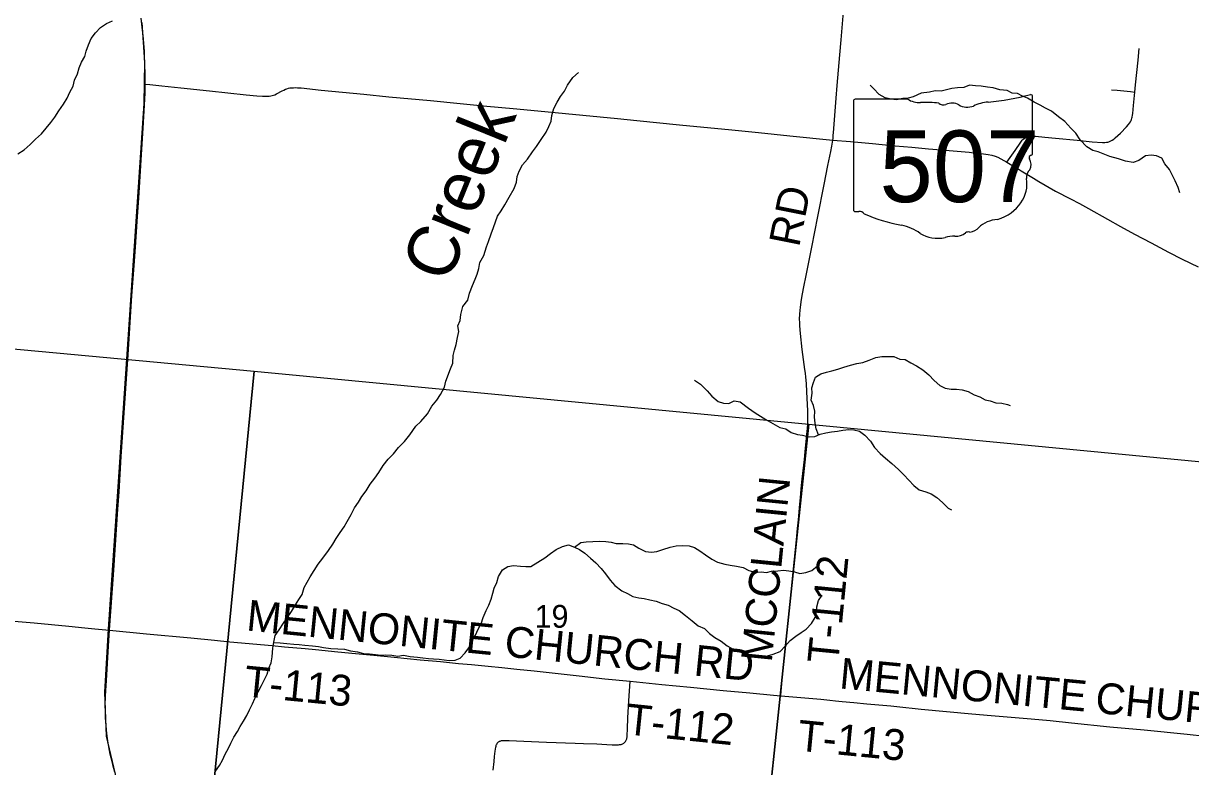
# Model space of a CAD drawing. Extents: x 0 to 1101, y 0 to 440.
# Drawn here: x 840.814 to 842.962, y 375.148 to 376.517 of the extents above; entities that cross this region are included whole.
import ezdxf

# ---------------------------------------------------------------- set-up
doc = ezdxf.new("R2010")
doc.units = 0
for name, color, linetype in [('GM_X_County_Road', 7, 'Continuous'), ('GM_X_Minor_River', 7, 'Continuous'), ('GM_X_Minor_River_Text', 7, 'Continuous'), ('GM_X_Rail_Line', 7, 'Continuous'), ('GM_X_Section', 7, 'Continuous'), ('GM_X_Section_Text', 7, 'Continuous'), ('GM_X_State_Location', 7, 'Continuous'), ('GM_X_State_Route', 7, 'Continuous'), ('GM_X_State_Shield', 7, 'Continuous'), ('GM_X_Township_Road', 7, 'Continuous'), ('GM_X_Township_Road_Text', 7, 'Continuous'), ('GM_X_US_Route', 7, 'Continuous')]:
    doc.layers.add(name, color=color, linetype=linetype)

msp = doc.modelspace()

# ---------------------------------------------------------------- linework, layer by layer
at = {"layer": 'GM_X_County_Road'}
msp.add_lwpolyline([(840.7823, 375.4177), (840.8341, 375.4129), (840.8655, 375.4099), (840.8973, 375.4069), (840.927, 375.4041), (840.9455, 375.4024), (840.9726, 375.3998)], dxfattribs=at)
at = {"layer": 'GM_X_Minor_River'}
for points in [[(840.8037, 376.2766), (840.8153, 376.2835), (840.8262, 376.2938), (840.836, 376.3034), (840.8473, 376.3134), (840.8556, 376.3238), (840.8642, 376.3338), (840.8721, 376.3439), (840.8793, 376.3558), (840.888, 376.3678), (840.8943, 376.3786), (840.8996, 376.3899), (840.9056, 376.4011), (840.9078, 376.4121), (840.9135, 376.4234), (840.9169, 376.4347), (840.9209, 376.4449), (840.9273, 376.4553), (840.9295, 376.4655), (840.9336, 376.4768), (840.9385, 376.4885), (840.9464, 376.4989), (840.9558, 376.5089), (840.9671, 376.5166), (840.9778, 376.5212)], [(841.6998, 376.1828), (841.7075, 376.1965), (841.7172, 376.2128), (841.7215, 376.2242), (841.7227, 376.2348), (841.7262, 376.2447), (841.7324, 376.2561), (841.7412, 376.2667), (841.7509, 376.28), (841.7582, 376.2898), (841.7667, 376.3027), (841.7756, 376.3163), (841.7806, 376.3266), (841.7849, 376.3368), (841.7865, 376.3467), (841.79, 376.3597), (841.7959, 376.3714), (841.802, 376.382), (841.8097, 376.3919), (841.8152, 376.4029), (841.8252, 376.4169), (841.8356, 376.426)], [(842.9415, 376.2046), (842.9386, 376.2145), (842.9334, 376.2268), (842.9277, 376.2379), (842.9225, 376.2478), (842.9142, 376.2578), (842.9086, 376.2682), (842.8987, 376.2728), (842.8892, 376.2737), (842.8786, 376.2726), (842.8663, 376.2644), (842.8556, 376.2603), (842.8415, 376.2631), (842.8286, 376.267), (842.8127, 376.2713), (842.8009, 376.2764), (842.7914, 376.2799), (842.7819, 376.2823), (842.7706, 376.2893), (842.7585, 376.3019), (842.7502, 376.3142), (842.7412, 376.3238), (842.7303, 376.3358), (842.7182, 376.3446), (842.7053, 376.3547), (842.6947, 376.3605), (842.6845, 376.3663), (842.6738, 376.3713), (842.6617, 376.3787), (842.6522, 376.3826), (842.6428, 376.3873), (842.6333, 376.3881), (842.6238, 376.3928), (842.6108, 376.3944), (842.5983, 376.398), (842.588, 376.3992), (842.5763, 376.4008), (842.566, 376.4013), (842.555, 376.4029), (842.5443, 376.3988), (842.5324, 376.3982), (842.5222, 376.3968), (842.5126, 376.3942), (842.5027, 376.392), (842.4917, 376.3925), (842.481, 376.3899), (842.4661, 376.3881), (842.4512, 376.3814), (842.4417, 376.3788), (842.4318, 376.3785), (842.4207, 376.376), (842.4104, 376.3768), (842.3998, 376.3792), (842.3888, 376.3858), (842.3782, 376.3969), (842.3718, 376.4031)], [(841.1677, 375.1402), (841.1747, 375.1508), (841.1801, 375.1606), (841.1852, 375.1712), (841.1913, 375.1822), (841.1956, 375.1917), (841.2014, 375.2027), (841.208, 375.213), (841.2126, 375.2225), (841.2188, 375.2319), (841.225, 375.2429), (841.2297, 375.2532), (841.2355, 375.2638), (841.2401, 375.2737), (841.246, 375.2862), (841.2521, 375.2976), (841.2568, 375.3078), (841.2626, 375.3188), (841.2658, 375.3295), (841.27, 375.3397), (841.272, 375.3507), (841.2729, 375.3667), (841.2749, 375.3778), (841.277, 375.39), (841.2843, 375.4002), (841.2924, 375.4123), (841.2993, 375.4225), (841.3074, 375.4343), (841.3148, 375.446), (841.3209, 375.4559), (841.3267, 375.4654), (841.3307, 375.4783), (841.3361, 375.4881), (841.3419, 375.4976), (841.3492, 375.5097), (841.3562, 375.5211), (841.3647, 375.5325), (841.3751, 375.5461), (841.3832, 375.5578), (841.3897, 375.5685), (841.3971, 375.5795), (841.404, 375.5901), (841.4098, 375.5999), (841.4171, 375.6128), (841.4233, 375.625), (841.4303, 375.6352), (841.4365, 375.6454), (841.4446, 375.656), (841.4519, 375.6685), (841.4604, 375.6795), (841.4681, 375.6901), (841.4762, 375.7026), (841.4851, 375.7147), (841.4947, 375.7242), (841.5039, 375.7359), (841.515, 375.7472), (841.5251, 375.7594), (841.5359, 375.7749), (841.5454, 375.7836), (841.5578, 375.7979), (841.5655, 375.812), (841.5747, 375.8233), (841.5817, 375.8336), (841.5887, 375.8472), (841.5914, 375.8582), (841.6, 375.8807), (841.6043, 375.8913), (841.6048, 375.905), (841.6072, 375.9149), (841.6103, 375.9255), (841.6127, 375.9385), (841.6151, 375.9491), (841.6136, 375.9598), (841.6175, 375.9697), (841.6188, 375.9807), (841.6227, 375.9952), (841.632, 376.0073), (841.6347, 376.0199), (841.6406, 376.0343), (841.6449, 376.0457), (841.6491, 376.0552), (841.6519, 376.0655), (841.6539, 376.0765), (841.6609, 376.0894), (841.666, 376.1054), (841.6695, 376.1152), (841.6745, 376.1293), (841.6792, 376.1407), (841.6827, 376.1513), (841.6866, 376.1616), (841.6932, 376.1714), (841.6998, 376.1828)], [(842.277, 375.7592), (842.2729, 375.7704), (842.2707, 375.7807), (842.2697, 375.7918), (842.2702, 375.8028), (842.268, 375.8131), (842.2635, 375.8231), (842.2655, 375.8356), (842.2648, 375.8456), (842.2676, 375.8558), (842.2711, 375.8653), (842.2814, 375.8717), (842.2914, 375.8747), (842.3013, 375.8769), (842.3123, 375.8798), (842.3238, 375.8835), (842.336, 375.8872), (842.3475, 375.8905), (842.3585, 375.8924), (842.3704, 375.8968), (842.3822, 375.9017), (842.3937, 375.9031), (842.4047, 375.9034), (842.4157, 375.9033), (842.4264, 375.8986), (842.4366, 375.8977), (842.4465, 375.8919), (842.4575, 375.8865), (842.4688, 375.8791), (842.4798, 375.8699), (842.49, 375.8595), (842.5002, 375.8503), (842.51, 375.8448), (842.5207, 375.8432), (842.5309, 375.8435), (842.5412, 375.8423), (842.5522, 375.8387), (842.5632, 375.8329), (842.5735, 375.8294), (842.5833, 375.8236), (842.5928, 375.8216), (842.6034, 375.8181), (842.6145, 375.8172), (842.6244, 375.8148), (842.6297, 375.8129)], [(842.0487, 375.8597), (842.0597, 375.8524), (842.0721, 375.8405), (842.0808, 375.8305), (842.0925, 375.8208), (842.102, 375.8177), (842.1119, 375.8168), (842.1215, 375.8217), (842.1329, 375.8197), (842.1484, 375.8081), (842.1601, 375.7996), (842.1798, 375.7872), (842.1927, 375.7803), (842.2056, 375.7725), (842.2166, 375.7701), (842.2264, 375.7636), (842.2382, 375.7596), (842.2477, 375.7588), (842.2598, 375.7553), (842.2701, 375.7563), (842.2801, 375.7604), (842.2904, 375.763), (842.3007, 375.7648), (842.3117, 375.7658), (842.3216, 375.7676), (842.3327, 375.7691), (842.3422, 375.7686), (842.3521, 375.7662), (842.3623, 375.7585), (842.3725, 375.7477), (842.38, 375.7359), (842.3902, 375.7251), (842.4, 375.7162), (842.4117, 375.7066), (842.4238, 375.6954), (842.434, 375.6858), (842.4434, 375.6758), (842.4521, 375.6658), (842.4623, 375.6581), (842.4741, 375.6546), (842.4839, 375.6507), (842.4945, 375.6441), (842.5051, 375.6348), (842.5153, 375.6245), (842.5217, 375.621)], [(841.2748, 375.3768), (841.2863, 375.3761), (841.2985, 375.3753), (841.3118, 375.374), (841.3214, 375.3732), (841.332, 375.3719), (841.3457, 375.371), (841.3567, 375.3694), (841.3662, 375.3678), (841.3799, 375.3661), (841.3925, 375.3656), (841.4047, 375.3644), (841.4161, 375.3616), (841.429, 375.36), (841.4396, 375.3568), (841.4507, 375.3563), (841.4621, 375.3547), (841.4716, 375.3539), (841.4811, 375.3541), (841.4921, 375.3537), (841.5028, 375.352), (841.5135, 375.3535), (841.5256, 375.3515), (841.5393, 375.3498), (841.5488, 375.349), (841.5591, 375.3477), (841.5686, 375.3469), (841.5789, 375.346), (841.5971, 375.3439), (841.6082, 375.3446), (841.6177, 375.3479), (841.627, 375.3581), (841.6354, 375.3699), (841.6393, 375.3794), (841.6459, 375.3904), (841.6509, 375.4018), (841.656, 375.4112), (841.6599, 375.423), (841.6657, 375.4359), (841.6704, 375.4454), (841.6747, 375.4568), (841.6778, 375.4675), (841.6802, 375.477), (841.6852, 375.4872), (841.6884, 375.4986), (841.6953, 375.5108), (841.7053, 375.5168), (841.7156, 375.5186), (841.7285, 375.5173), (841.7384, 375.5168), (841.7479, 375.5167), (841.7602, 375.5246), (841.7732, 375.5329), (841.7839, 375.5408), (841.7943, 375.5483), (841.8061, 375.5536), (841.8168, 375.5569), (841.8278, 375.5526), (841.8373, 375.5483), (841.8471, 375.5414), (841.8573, 375.5325), (841.8675, 375.5237), (841.8773, 375.5133), (841.8852, 375.5033), (841.8935, 375.4918), (841.9022, 375.4818), (841.915, 375.4721), (841.9253, 375.4671), (841.9355, 375.4617), (841.9461, 375.4593), (841.956, 375.458), (841.9663, 375.4553), (841.9781, 375.4529), (841.9891, 375.449), (842.0005, 375.4458), (842.0107, 375.4404), (842.0206, 375.4357), (842.0323, 375.4265), (842.0444, 375.4168), (842.0557, 375.4079), (842.0671, 375.4029), (842.0762, 375.3933), (842.0864, 375.3859), (842.0977, 375.3797), (842.1091, 375.3709), (842.1189, 375.3654), (842.1288, 375.3612), (842.1406, 375.3565), (842.15, 375.3533), (842.163, 375.3525), (842.1736, 375.3516), (842.1832, 375.3527), (842.1938, 375.3552), (842.2061, 375.3605), (842.2153, 375.3703), (842.2249, 375.3809), (842.2349, 375.3888), (842.2448, 375.3952), (842.2544, 375.4016), (842.264, 375.4121), (842.2706, 375.4228)], [(841.828, 375.5525), (841.8397, 375.5609), (841.8496, 375.5623), (841.8618, 375.5626), (841.8732, 375.5632), (841.8854, 375.5628), (841.8953, 375.5615), (841.9048, 375.5591), (841.917, 375.559), (841.9272, 375.5586), (841.9367, 375.5569), (841.9466, 375.5504), (841.9587, 375.5445), (841.9694, 375.5433), (841.9793, 375.5444), (841.9907, 375.5484), (842.0037, 375.5525), (842.0148, 375.5547), (842.027, 375.5554), (842.0388, 375.5552), (842.0486, 375.5521), (842.0585, 375.5455), (842.0687, 375.5386), (842.0808, 375.5301), (842.091, 375.5246), (842.1043, 375.5211), (842.1142, 375.5195), (842.126, 375.5175), (842.1382, 375.5151), (842.1488, 375.5093), (842.1598, 375.5065), (842.1716, 375.5068), (842.1811, 375.5059), (842.1906, 375.5085), (842.2021, 375.5091), (842.2127, 375.5102), (842.2226, 375.5086), (842.2329, 375.5073), (842.2428, 375.5042), (842.2538, 375.506), (842.2649, 375.5093), (842.2749, 375.518), (842.2745, 375.5165)], [(842.2706, 375.4228), (842.273, 375.433), (842.2738, 375.4429), (842.2766, 375.454), (842.2839, 375.4638)]]:
    msp.add_lwpolyline(points, dxfattribs=at)
at = {"layer": 'GM_X_Rail_Line'}
msp.add_lwpolyline([(841.5195, 373.3971), (841.577, 374.1201), (841.5739, 374.197), (841.5566, 374.279), (841.5303, 374.3497), (841.4897, 374.4246), (841.4299, 374.5037), (841.2374, 374.7544), (841.0769, 374.9681), (841.0188, 375.0513), (840.9858, 375.1239), (840.967, 375.2046), (840.9639, 375.2857), (840.9706, 375.4017), (841.0359, 376.3692), (841.0375, 376.4451), (841.0327, 376.5183)], dxfattribs=at)
at = {"layer": 'GM_X_Section'}
for points in [[(841.2384, 375.8766), (841.1413, 374.878), (840.1883, 374.9685), (840.266, 375.9665)], [(842.2594, 375.7788), (842.1535, 374.7776), (841.1413, 374.878), (841.2384, 375.8766)], [(842.2594, 375.7788), (843.3348, 375.6757), (843.2377, 374.6786), (842.1535, 374.7776)]]:
    msp.add_lwpolyline(points, close=True, dxfattribs=at)
at = {"layer": 'GM_X_State_Route'}
for points in [[(841.0381, 376.4047), (841.0466, 376.4038), (841.0689, 376.4016), (841.1035, 376.3979), (841.1566, 376.3923), (841.224, 376.3851), (841.2438, 376.3832), (841.2538, 376.3826), (841.2588, 376.3825), (841.2622, 376.3826), (841.2664, 376.3828), (841.269, 376.3831), (841.2715, 376.3836), (841.2744, 376.3844), (841.2764, 376.3853), (841.2799, 376.3869), (841.2901, 376.3925), (841.2931, 376.3939), (841.2963, 376.3952), (841.2988, 376.3961), (841.3017, 376.397), (841.3045, 376.3976), (841.3075, 376.398), (841.3111, 376.3982), (841.3145, 376.3983), (841.3185, 376.3981), (841.3253, 376.3976), (841.3617, 376.3937), (841.4403, 376.386), (841.4861, 376.3816), (841.5628, 376.3744), (841.6179, 376.3689), (841.6667, 376.3642), (841.715, 376.3597), (841.7608, 376.3555), (841.8115, 376.3504), (841.9068, 376.3413), (841.9426, 376.3378), (842.0212, 376.3299), (842.1177, 376.3204), (842.1665, 376.3155), (842.224, 376.3097), (842.3031, 376.3016), (842.3358, 376.2989), (842.3761, 376.2952), (842.4181, 376.2913), (842.4485, 376.2885), (842.4794, 376.2857), (842.5023, 376.2837), (842.5542, 376.2792), (842.5678, 376.2779), (842.5807, 376.2764), (842.5893, 376.2752), (842.5959, 376.2737), (842.6018, 376.272), (842.6069, 376.27), (842.6125, 376.2674), (842.6234, 376.2612), (842.6462, 376.2474)], [(842.6462, 376.2474), (842.6496, 376.2453), (842.6724, 376.2314), (842.6825, 376.2255), (842.7132, 376.2079), (842.7407, 376.1935), (842.7571, 376.1848), (842.7735, 376.1758), (842.8087, 376.1562), (842.8325, 376.1427), (842.8582, 376.1288), (842.8889, 376.1125), (842.9207, 376.0955), (842.9463, 376.0827), (842.9753, 376.0686)]]:
    msp.add_lwpolyline(points, dxfattribs=at)
at = {"layer": 'GM_X_State_Shield'}
for p, q in [((842.3413, 376.3736), (842.3413, 376.1735)), ((842.4411, 376.3771), (842.3446, 376.3771)), ((842.6709, 376.2774), (842.6709, 376.3821)), ((842.6709, 376.2774), (842.6709, 376.2774))]:
    msp.add_line(p, q, dxfattribs=at)
for centre, major_axis, start_param, end_param in [((842.3451, 376.3741), (0.00382, 0), 1.712693, 3.28349), ((842.4641, 376.4003), (0.037, 0), 4.042523, 4.731795), ((842.4764, 376.2647), (0.133, 0), 1.404758, 1.657858), ((842.5065, 376.3751), (0.0107, 0), 3.836095, 5.185415), ((842.5222, 376.352), (0.0222, 0), 0.950623, 2.079405), ((842.5981, 376.316), (0.0703, 0), 1.699011, 2.107814), ((842.5535, 376.6499), (0.3495, 0), 4.814394, 5.042369), ((842.6673, 376.3825), (0.00367, 0), 6.141152, 7.989035), ((842.5509, 376.3837), (0.0267, 0), 4.081561, 5.145723), ((842.6701, 376.2697), (0.00568, 0), 1.883978, 3.671073), ((842.6339, 376.2564), (0.0341, 0), 5.934695, 6.695948), ((842.667, 376.277), (0.00393, 0), 5.05454, 6.418171), ((842.6841, 376.2336), (0.0248, 0), 2.387724, 3.262537), ((842.5731, 376.2202), (0.0874, 0), 5.101752, 6.440018), ((842.3451, 376.1731), (0.00385, 0), 3.00124, 4.508301), ((842.3457, 376.1936), (0.0294, 0), 4.665946, 4.897461), ((842.3517, 376.162), (0.0106, 0), 0.519207, 1.627899), ((842.4856, 376.3418), (0.2524, 0), 4.195997, 4.488961), ((842.61, 376.1173), (0.0479, 0), 1.647645, 2.488434), ((842.4103, 376.0836), (0.079, 0), 0.823519, 1.323587), ((842.5525, 376.1266), (0.00752, 0), 1.147584, 2.315152), ((842.5493, 376.1541), (0.0282, 0), 4.937069, 5.64225), ((842.4957, 376.161), (0.0501, 0), 4.026481, 4.996735), ((842.5247, 376.0918), (0.0412, 0), 1.495662, 1.94098), ((842.5283, 376.146), (0.0267, 0), 4.691044, 5.507374)]:
    msp.add_ellipse(centre, major_axis=major_axis, ratio=0.8, start_param=start_param, end_param=end_param, dxfattribs=at)
at = {"layer": 'GM_X_Township_Road'}
for points in [[(842.3031, 376.3016), (842.3036, 376.3049), (842.3041, 376.3105), (842.3045, 376.3152), (842.3093, 376.379), (842.3111, 376.4019), (842.3163, 376.4588), (842.3186, 376.486), (842.3229, 376.538), (842.3274, 376.5894), (842.3316, 376.6395), (842.3365, 376.6965), (842.3399, 376.7379), (842.3419, 376.7625), (842.3436, 376.7862)], [(842.859, 376.39), (842.8603, 376.4037), (842.8651, 376.4491), (842.8672, 376.4701)], [(842.6234, 376.2612), (842.6385, 376.2828), (842.6492, 376.298), (842.6518, 376.3014), (842.6531, 376.3027), (842.6545, 376.304), (842.6563, 376.3053), (842.6576, 376.306), (842.6591, 376.3068), (842.661, 376.3076), (842.6628, 376.3082), (842.6644, 376.3086), (842.6662, 376.3088), (842.6688, 376.3091), (842.6714, 376.3091), (842.6761, 376.3089), (842.6934, 376.3074), (842.7132, 376.3054), (842.7527, 376.3015), (842.7805, 376.2987), (842.7996, 376.297), (842.8019, 376.297), (842.8038, 376.2972), (842.8066, 376.2976), (842.8091, 376.298), (842.8109, 376.2986), (842.8137, 376.2999), (842.8174, 376.3018), (842.8201, 376.3036), (842.8228, 376.3057), (842.8323, 376.3147), (842.8433, 376.3262), (842.8472, 376.3305), (842.8492, 376.333), (842.8507, 376.3352), (842.8521, 376.3378), (842.8529, 376.3396), (842.8536, 376.3419), (842.8541, 376.3441), (842.8547, 376.3475), (842.8551, 376.3509), (842.8565, 376.3654), (842.859, 376.39)], [(842.8158, 376.3945), (842.8265, 376.3935), (842.8387, 376.3923), (842.851, 376.3909), (842.859, 376.39)], [(842.2076, 375.279), (842.2084, 375.2874), (842.2109, 375.3146), (842.2126, 375.3336), (842.2169, 375.3746), (842.2206, 375.4103), (842.2239, 375.4437), (842.228, 375.4826), (842.2309, 375.5123), (842.2363, 375.566), (842.2383, 375.5865), (842.2398, 375.6025), (842.2425, 375.6316), (842.2436, 375.6433), (842.2444, 375.6513), (842.2452, 375.66), (842.247, 375.6779), (842.2509, 375.714), (842.2525, 375.7283), (842.2542, 375.7465), (842.2555, 375.7598), (842.2565, 375.7707), (842.257, 375.7792), (842.2574, 375.7903), (842.257, 375.8036), (842.2554, 375.8385), (842.2546, 375.8534), (842.2536, 375.8656), (842.2528, 375.8726), (842.2518, 375.8797), (842.2467, 375.916), (842.2436, 375.9455), (842.2427, 375.9599), (842.2424, 375.9658), (842.2422, 375.9724), (842.2426, 375.9811), (842.2431, 375.9884), (842.2436, 375.9933), (842.2449, 376.004), (842.2462, 376.0122), (842.2492, 376.0283), (842.2547, 376.0557), (842.2645, 376.1044), (842.2758, 376.1612), (842.2874, 376.2197), (842.2943, 376.255), (842.2994, 376.281), (842.3013, 376.2903), (842.3026, 376.2979), (842.3031, 376.3016)], [(840.9726, 375.3998), (841.0407, 375.3929), (841.1218, 375.3853), (841.1657, 375.3812), (841.1941, 375.3785), (841.2715, 375.3714), (841.2944, 375.3693), (841.3327, 375.3657), (841.3513, 375.3638), (841.3927, 375.36), (841.4249, 375.357), (841.4589, 375.3537), (841.496, 375.35), (841.5442, 375.3453), (841.5813, 375.3418), (841.6147, 375.3386), (841.6382, 375.3363), (841.6691, 375.3334), (841.6945, 375.3308), (841.7216, 375.3278), (841.7538, 375.3248), (841.7815, 375.322), (841.8364, 375.3154), (841.8839, 375.3101), (841.9303, 375.3057)], [(841.8873, 375.1894), (841.8975, 375.1889), (841.9069, 375.1887), (841.9089, 375.1888), (841.9106, 375.189), (841.9123, 375.1892), (841.9136, 375.1895), (841.9153, 375.19), (841.9166, 375.1906), (841.9177, 375.1912), (841.9187, 375.1918), (841.9201, 375.193), (841.9211, 375.194), (841.9218, 375.1949), (841.9224, 375.196), (841.923, 375.197), (841.9236, 375.1984), (841.9241, 375.1999), (841.9245, 375.2016), (841.9247, 375.203), (841.9249, 375.2046), (841.925, 375.206), (841.9254, 375.2178), (841.9263, 375.2383), (841.9281, 375.2699), (841.9303, 375.3057)], [(841.9303, 375.3057), (841.9885, 375.2998), (842.0412, 375.2947), (842.1017, 375.2888), (842.1506, 375.2841), (842.1941, 375.2801), (842.2076, 375.279)], [(842.2076, 375.279), (842.2518, 375.2752), (842.2814, 375.2724), (842.2975, 375.2707), (842.308, 375.2696), (842.3204, 375.2684), (842.342, 375.2664), (842.3661, 375.2641), (842.3804, 375.263), (842.4101, 375.2602), (842.4213, 375.2591), (842.4657, 375.2545), (842.5124, 375.25), (842.5589, 375.2459), (842.5945, 375.2428), (842.6387, 375.2388), (842.6679, 375.2362), (842.7033, 375.2331), (842.7427, 375.229), (842.8129, 375.2219), (842.8764, 375.216), (842.9555, 375.2082), (842.9888, 375.2047)], [(841.6783, 375.1417), (841.6799, 375.1577), (841.6809, 375.167), (841.6823, 375.1769), (841.6834, 375.1842), (841.6838, 375.186), (841.6841, 375.1877), (841.6846, 375.189), (841.685, 375.1899), (841.6854, 375.1907), (841.6859, 375.1915), (841.6865, 375.1922), (841.687, 375.1928), (841.6878, 375.1935), (841.6884, 375.1941), (841.6891, 375.1945), (841.69, 375.1951), (841.691, 375.1955), (841.6924, 375.1961), (841.6938, 375.1965), (841.6952, 375.1967), (841.6966, 375.1969), (841.6985, 375.1969), (841.7007, 375.1969), (841.7076, 375.1966), (841.7349, 375.1955), (841.7765, 375.1937), (841.8293, 375.1917), (841.8448, 375.1912), (841.869, 375.1902), (841.8873, 375.1894)]]:
    msp.add_lwpolyline(points, dxfattribs=at)
at = {"layer": 'GM_X_US_Route'}
msp.add_lwpolyline([(840.9825, 375.1383), (840.9793, 375.1496), (840.9771, 375.1581), (840.9736, 375.1713), (840.971, 375.1847), (840.9691, 375.1962), (840.9676, 375.2093), (840.9661, 375.2235), (840.9652, 375.2382), (840.9648, 375.2502), (840.9647, 375.2612), (840.9652, 375.2786), (840.967, 375.3072), (840.9708, 375.3704), (840.9726, 375.3998), (840.9748, 375.4342), (840.9802, 375.5103), (840.9834, 375.557), (840.9877, 375.6226), (840.9899, 375.6546), (840.994, 375.7193), (841.0049, 375.8801), (841.0066, 375.9066), (841.0097, 375.9562), (841.0136, 376.0151), (841.0176, 376.0708), (841.02, 376.1047), (841.0239, 376.1609), (841.0262, 376.1948), (841.0298, 376.2551), (841.0331, 376.304), (841.0343, 376.3236), (841.0357, 376.3449), (841.037, 376.366), (841.0379, 376.3883), (841.0381, 376.4009), (841.0381, 376.4047), (841.038, 376.4234), (841.0376, 376.44), (841.037, 376.4561), (841.0366, 376.4645), (841.036, 376.473), (841.0343, 376.4941), (841.0334, 376.5043), (841.0321, 376.5151), (841.0308, 376.5261)], dxfattribs=at)

# ---------------------------------------------------------------- texts
at = {"layer": 'GM_X_Minor_River_Text'}
msp.add_text('Creek', height=0.09468, rotation=67.9153, dxfattribs=at).set_placement((841.5952, 376.0355))
at = {"layer": 'GM_X_Section_Text'}
msp.add_text('19', height=0.04186, rotation=0, dxfattribs=at).set_placement((841.7547, 375.4042))
at = {"layer": 'GM_X_State_Location'}
for s in ['s', 'r']:
    msp.add_text(s, height=0.000189, dxfattribs=at).set_placement((842.5024, 376.2603))
msp.add_text('507', height=0.000189, rotation=0, dxfattribs=at).set_placement((842.4356, 376.2465))
at = {"layer": 'GM_X_State_Shield'}
msp.add_text('507', height=0.13184, dxfattribs=at).set_placement((842.3892, 376.1876))
at = {"layer": 'GM_X_Township_Road_Text'}
for s, height, rotation, p in [('RD', 0.05682, 78.5951, (842.2411, 376.1031)), ('MCCLAIN', 0.05682, 84.2596, (842.1908, 375.3393)), ('T-112', 0.05682, 84.4016, (842.3129, 375.3366)), ('MENNONITE CHURCH RD', 0.056818, 354.2496, (841.2229, 375.3993)), ('MENNONITE', 0.05682, 354.5985, (842.314, 375.2926)), ('T-113', 0.05682, 354.456, (841.2182, 375.2781)), ('CHURCH', 0.05682, 354.4001, (842.7845, 375.2477)), ('T-112', 0.05682, 354.1221, (841.921, 375.2082)), ('T-113', 0.05682, 354.4553, (842.2365, 375.1781))]:
    msp.add_text(s, height=height, rotation=rotation, dxfattribs=at).set_placement(p)

doc.saveas('drawing.dxf')
